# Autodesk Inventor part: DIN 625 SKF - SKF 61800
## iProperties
Created: 2008-01
Part Number: DIN 625 SKF - SKF 61800
Material: Steel, Mild
Description: Single row ball bearings
Document SubType Name: Modeling
Standard: DIN 625
Designer: latalom
Standards Organization: DIN
Language: en-US
Size Designation: SKF 61800
Categories: <MemberInstance><Categories><Category DisplayName="Shaft Parts" InternalName="7f7aeb1f-a693-4053-b835-cee3144e0d98" Mnemonic="SHFT"><Category DisplayName="Beari
Density: 7.86 g/cm^3
IsCustomPart: 0
Author: latalom
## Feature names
1. Revolution1
2. Revolution2
3. Revolution3
4. PolarArray1 [Circular Pattern]
5. Fillet1
